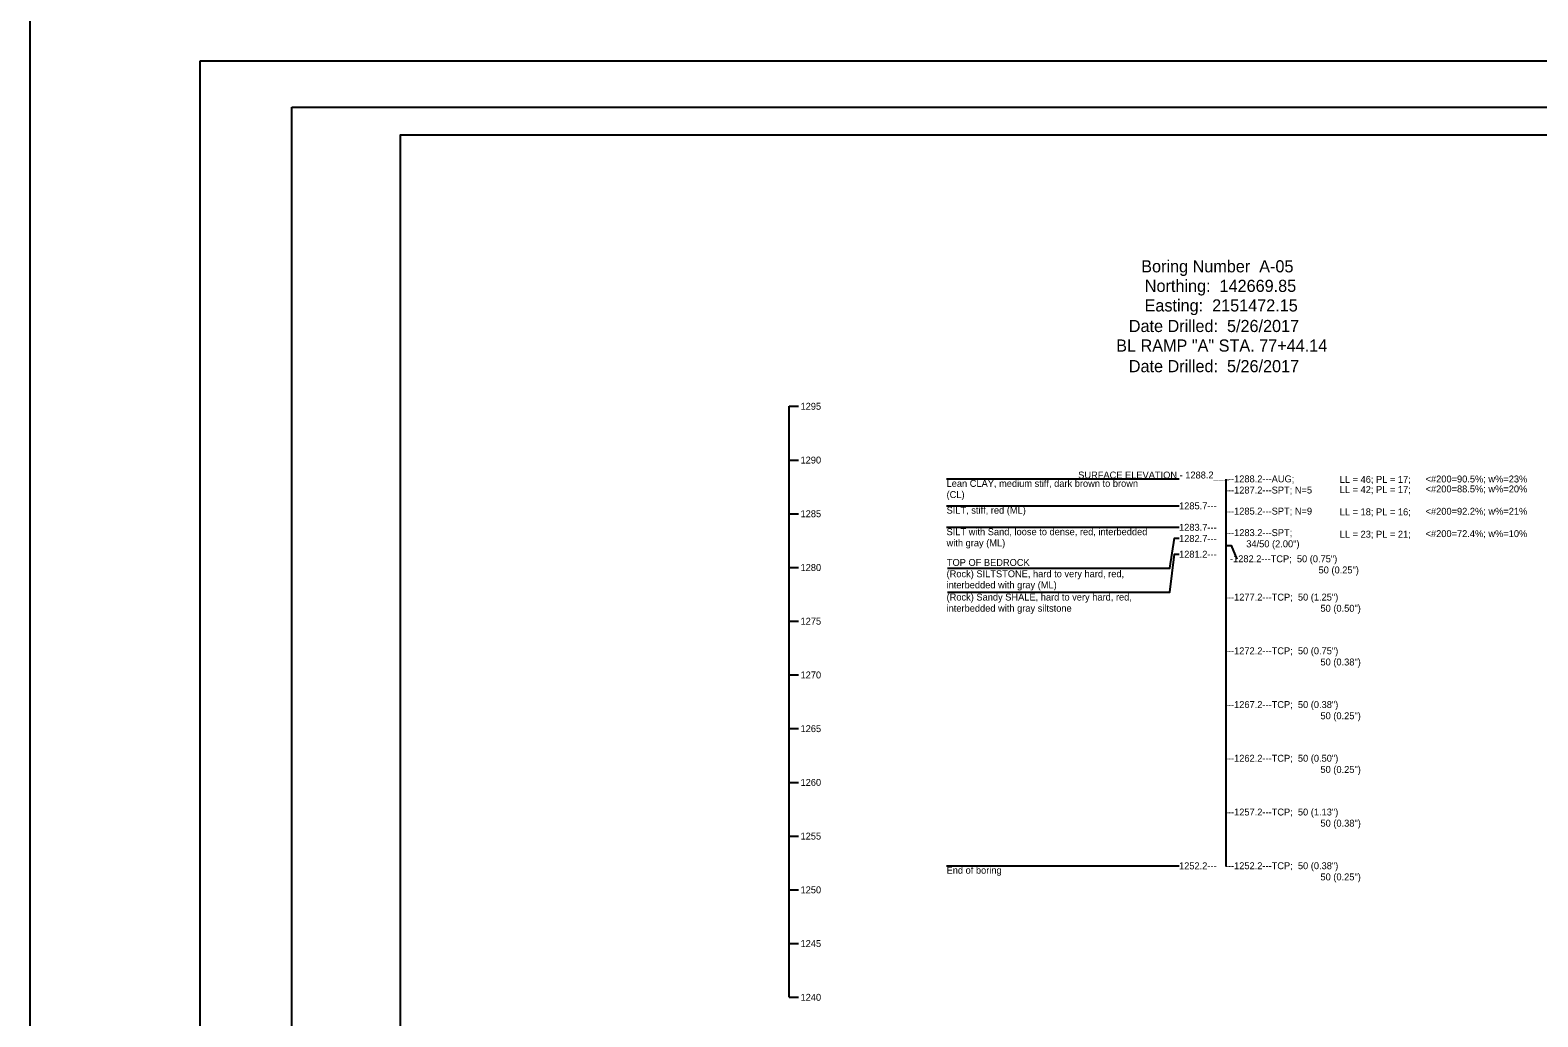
# Model space of a CAD drawing. Extents: x 2150161.5 to 2150203.1, y 143779.5 to 143868.5.
# Drawn here: x 2150161.53 to 2150188.52, y 143790.44 to 143808.09 of the extents above; entities that cross this region are included whole.
import ezdxf

# ---------------------------------------------------------------- set-up
doc = ezdxf.new("R2010")
doc.units = 0
for name, color, linetype in [('Default', 7, 'Continuous'), ('S', 7, 'Continuous'), ('SHT_Plot_Shape_Full', 7, 'Continuous'), ('SHT_Plot_Shape_Half', 7, 'Continuous'), ('SHT_Sheet_Border', 7, 'Continuous')]:
    doc.layers.add(name, color=color, linetype=linetype)

msp = doc.modelspace()

# ---------------------------------------------------------------- linework, layer by layer
at = {"layer": 'Default'}
msp.add_line((2150175.119, 143790.786), (2150175.119, 143801.363), dxfattribs=at)
for points in [[(2150175.119, 143801.363), (2150175.285, 143801.363)], [(2150175.119, 143800.401), (2150175.285, 143800.401)], [(2150177.937, 143800.062), (2150182.104, 143800.062)], [(2150182.937, 143800.061), (2150182.937, 143793.139)], [(2150182.937, 143800.061), (2150182.937, 143798.869), (2150183.034, 143798.869), (2150183.131, 143798.628)], [(2150175.119, 143799.44), (2150175.285, 143799.44)], [(2150177.937, 143799.581), (2150182.104, 143799.581)], [(2150177.937, 143799.197), (2150182.104, 143799.197)], [(2150177.956, 143798.465), (2150181.937, 143798.465), (2150182.02, 143799.004), (2150182.104, 143799.004)], [(2150177.956, 143798.038), (2150181.937, 143798.038), (2150182.02, 143798.716), (2150182.104, 143798.716)], [(2150175.119, 143798.478), (2150175.285, 143798.478)], [(2150175.119, 143797.517), (2150175.285, 143797.517)], [(2150175.119, 143796.555), (2150175.285, 143796.555)], [(2150175.119, 143795.594), (2150175.285, 143795.594)], [(2150175.119, 143794.632), (2150175.285, 143794.632)], [(2150175.119, 143793.671), (2150175.285, 143793.671)], [(2150177.937, 143793.139), (2150182.104, 143793.139)], [(2150175.119, 143792.709), (2150175.285, 143792.709)], [(2150175.119, 143791.748), (2150175.285, 143791.748)], [(2150175.119, 143791.748), (2150175.285, 143791.748)], [(2150175.119, 143790.786), (2150175.285, 143790.786)], [(2150175.119, 143790.786), (2150175.285, 143790.786)], [(2150175.119, 143790.786), (2150175.285, 143790.786)], [(2150175.119, 143790.786), (2150175.285, 143790.786)]]:
    msp.add_lwpolyline(points, dxfattribs=at)
at = {"layer": 'S'}
msp.add_lwpolyline([(2150161.53, 143868.477), (2150203.071, 143868.477), (2150203.071, 143779.536), (2150161.53, 143779.536)], close=True, dxfattribs=at)
at = {"layer": 'SHT_Plot_Shape_Full'}
msp.add_lwpolyline([(2150164.575, 143807.544), (2150200.575, 143807.544), (2150200.575, 143783.544), (2150164.575, 143783.544)], close=True, dxfattribs=at)
at = {"layer": 'SHT_Plot_Shape_Half'}
msp.add_lwpolyline([(2150166.212, 143806.719), (2150200.212, 143806.719), (2150200.212, 143784.719), (2150166.212, 143784.719)], close=True, dxfattribs=at)
at = {"layer": 'SHT_Sheet_Border'}
msp.add_lwpolyline([(2150199.662, 143785.219), (2150168.162, 143785.219), (2150168.162, 143806.219), (2150199.662, 143806.219)], close=True, dxfattribs=at)

# ---------------------------------------------------------------- texts
at = {"layer": 'Default'}
for s, height, p in [('Boring Number  A-05', 0.217, (2150181.422, 143803.76)), ('Northing:  142669.85', 0.217, (2150181.486, 143803.41)), ('Easting:  2151472.15', 0.217, (2150181.482, 143803.06)), ('Date Drilled:  5/26/2017', 0.217, (2150181.2, 143802.692)), ('BL RAMP "A" STA. 77+44.14', 0.217, (2150180.974, 143802.342)), ('Date Drilled:  5/26/2017', 0.217, (2150181.2, 143801.973)), ('1295', 0.124, (2150175.322, 143801.301)), ('1290', 0.124, (2150175.322, 143800.339)), ('SURFACE ELEVATION - 1288.2___', 0.124, (2150180.294, 143800.071)), ('Lean CLAY, medium stiff, dark brown to brown', 0.124, (2150177.937, 143799.921)), ('---1288.2---AUG;', 0.124, (2150182.919, 143800.002)), ('---1287.2---SPT; N=5', 0.124, (2150182.919, 143799.802)), ('LL = 46; PL = 17;', 0.124, (2150184.976, 143799.993)), ('LL = 42; PL = 17;', 0.124, (2150184.976, 143799.812)), ('<#200=90.5%; w%=23%', 0.124, (2150186.513, 143800)), ('<#200=88.5%; w%=20%', 0.124, (2150186.513, 143799.822)), ('(CL)', 0.124, (2150177.937, 143799.721)), ('1285.7---', 0.124, (2150182.099, 143799.519)), ('1285', 0.124, (2150175.322, 143799.378)), ('SILT, stiff, red (ML)', 0.124, (2150177.937, 143799.441)), ('---1285.2---SPT; N=9', 0.124, (2150182.919, 143799.425)), ('LL = 18; PL = 16;', 0.124, (2150184.976, 143799.412)), ('<#200=92.2%; w%=21%', 0.124, (2150186.513, 143799.422)), ('SILT with Sand, loose to dense, red, interbedded', 0.124, (2150177.937, 143799.056)), ('1283.7---', 0.124, (2150182.099, 143799.135)), ('1282.7---', 0.124, (2150182.099, 143798.935)), ('---1283.2---SPT;', 0.124, (2150182.919, 143799.04)), ('LL = 23; PL = 21;', 0.124, (2150184.976, 143799.012)), ('<#200=72.4%; w%=10%', 0.124, (2150186.513, 143799.022)), ('with gray (ML)', 0.124, (2150177.937, 143798.856)), ('1281.2---', 0.124, (2150182.099, 143798.654)), ('34/50 (2.00")', 0.124, (2150183.303, 143798.84)), ('1280', 0.124, (2150175.322, 143798.416)), ('TOP OF BEDROCK', 0.124, (2150177.942, 143798.506)), ('  -1282.2---TCP;  50 (0.75")', 0.124, (2150182.919, 143798.572)), ('(Rock) SILTSTONE, hard to very hard, red,', 0.124, (2150177.937, 143798.304)), ('50 (0.25")', 0.124, (2150184.597, 143798.372)), ('(Rock) Sandy SHALE, hard to very hard, red,', 0.124, (2150177.937, 143797.887)), ('interbedded with gray (ML)', 0.124, (2150177.937, 143798.104)), ('---1277.2---TCP;  50 (1.25")', 0.124, (2150182.919, 143797.886)), ('interbedded with gray siltstone', 0.124, (2150177.937, 143797.687)), ('50 (0.50")', 0.124, (2150184.631, 143797.686)), ('1275', 0.124, (2150175.322, 143797.455)), ('---1272.2---TCP;  50 (0.75")', 0.124, (2150182.919, 143796.925)), ('1270', 0.124, (2150175.322, 143796.493)), ('50 (0.38")', 0.124, (2150184.631, 143796.725)), ('---1267.2---TCP;  50 (0.38")', 0.124, (2150182.919, 143795.963)), ('50 (0.25")', 0.124, (2150184.631, 143795.763)), ('1265', 0.124, (2150175.322, 143795.532)), ('---1262.2---TCP;  50 (0.50")', 0.124, (2150182.919, 143795.002)), ('50 (0.25")', 0.124, (2150184.631, 143794.802)), ('1260', 0.124, (2150175.322, 143794.57)), ('---1257.2---TCP;  50 (1.13")', 0.124, (2150182.919, 143794.04)), ('50 (0.38")', 0.124, (2150184.631, 143793.84)), ('1255', 0.124, (2150175.322, 143793.609)), ('End of boring', 0.124, (2150177.937, 143792.998)), ('1252.2---', 0.124, (2150182.099, 143793.077)), ('---1252.2---TCP;  50 (0.38")', 0.124, (2150182.919, 143793.079)), ('50 (0.25")', 0.124, (2150184.631, 143792.879)), ('1250', 0.124, (2150175.322, 143792.647)), ('1245', 0.124, (2150175.322, 143791.686)), ('1240', 0.124, (2150175.322, 143790.724))]:
    msp.add_text(s, height=height, dxfattribs=at).set_placement(p)

doc.saveas('drawing.dxf')
